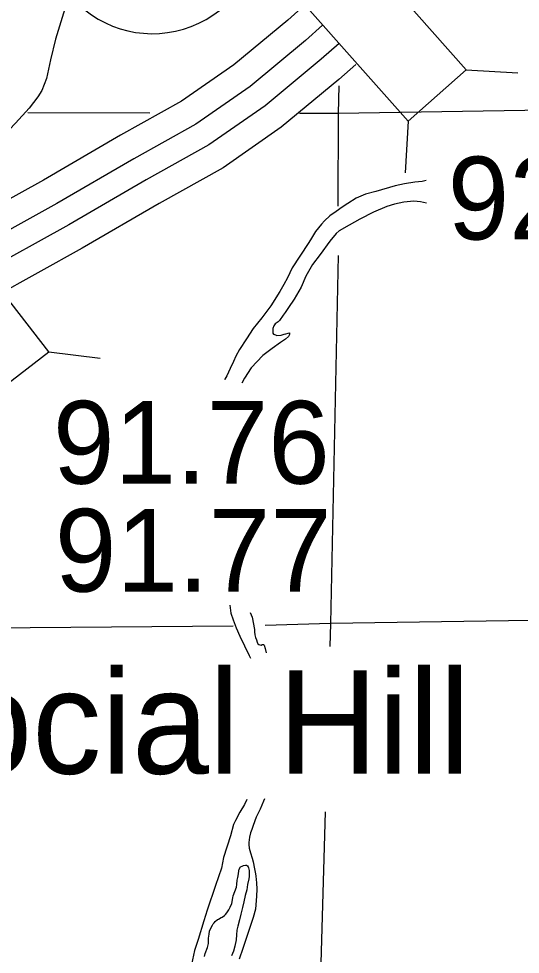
# Model space of a CAD drawing. Extents: x 22866 to 28196, y 1324810 to 1328105.
# Drawn here: x 24036.2 to 24121.3, y 1326735.6 to 1326894.3 of the extents above; entities that cross this region are included whole.
import ezdxf

# ---------------------------------------------------------------- set-up
doc = ezdxf.new("R2010")
doc.units = 0
for name, color, linetype in [('Level 10', 7, 'Continuous'), ('Level 19', 7, 'Continuous'), ('Level 20', 7, 'Continuous'), ('Level 24', 7, 'Continuous'), ('Level 4', 7, 'Continuous'), ('Level 5', 7, 'Continuous'), ('Level 58', 7, 'Continuous'), ('Level 9', 7, 'Continuous')]:
    doc.layers.add(name, color=color, linetype=linetype)

msp = doc.modelspace()

# ---------------------------------------------------------------- linework, layer by layer
at = {"layer": 'Level 10'}
msp.add_lwpolyline([(24043.99, 1326896), (24042.39, 1326890.87), (24041.54, 1326887.37), (24040.9, 1326884.19), (24040.08, 1326882.13), (24039.42, 1326881.07), (24037.95, 1326879.17), (24035.6, 1326876.6), (24032.53, 1326873.43), (24029.62, 1326870.47), (24026.22, 1326867.23), (24022.48, 1326863.48), (24018.35, 1326859.59), (24014.75, 1326856.32), (24011.73, 1326854.08), (24008.05, 1326851.01), (24004.29, 1326847.14), (24000.82, 1326843.16), (23997.45, 1326838.64), (23995.71, 1326836.61), (23993.79, 1326834.13), (23992.44, 1326832.42)], dxfattribs=at)
msp.add_lwpolyline([(24043.99, 1326896), (24042.39, 1326890.87), (24041.54, 1326887.37), (24040.9, 1326884.19), (24040.08, 1326882.13), (24039.42, 1326881.07), (24037.95, 1326879.17), (24035.6, 1326876.6), (24032.53, 1326873.43), (24029.62, 1326870.47), (24026.22, 1326867.23), (24022.48, 1326863.48), (24018.35, 1326859.59), (24014.75, 1326856.32), (24011.73, 1326854.08), (24008.05, 1326851.01), (24004.29, 1326847.14), (24000.82, 1326843.16), (23997.45, 1326838.64), (23995.71, 1326836.61), (23993.79, 1326834.13), (23992.44, 1326832.42)], dxfattribs=at)
at = {"layer": 'Level 19'}
for points in [[(24084.7, 1326896.62), (24081.85, 1326894.1), (24072.69, 1326886.51), (24063.82, 1326880.35), (24053.45, 1326874.56), (24040.37, 1326866.96), (24025.08, 1326858.49), (24021.08, 1326855.99), (24017.17, 1326852.96), (24013.54, 1326849.64), (24007.92, 1326844.77), (24003.92, 1326840.65), (23998.58, 1326834.2), (23993.67, 1326828.38), (23988.76, 1326822.21), (23982.91, 1326815.43)], [(24084.7, 1326896.62), (24081.85, 1326894.1), (24072.69, 1326886.51), (24063.82, 1326880.35), (24053.45, 1326874.56), (24040.37, 1326866.96), (24025.08, 1326858.49), (24021.08, 1326855.99), (24017.17, 1326852.96), (24013.54, 1326849.64), (24007.92, 1326844.77), (24003.92, 1326840.65), (23998.58, 1326834.2), (23993.67, 1326828.38), (23988.76, 1326822.21), (23982.91, 1326815.43)], [(24087.74, 1326893.21), (24084.83, 1326890.62), (24075.46, 1326882.86), (24066.24, 1326876.47), (24055.71, 1326870.59), (24042.63, 1326862.99), (24027.4, 1326854.55), (24023.7, 1326852.24), (24020.12, 1326849.46), (24016.58, 1326846.23), (24011.07, 1326841.45), (24007.33, 1326837.6), (24002.09, 1326831.27), (23997.21, 1326825.49), (23992.29, 1326819.29), (23986.36, 1326812.43)], [(24087.74, 1326893.21), (24084.83, 1326890.62), (24075.46, 1326882.86), (24066.24, 1326876.47), (24055.71, 1326870.59), (24042.63, 1326862.99), (24027.4, 1326854.55), (24023.7, 1326852.24), (24020.12, 1326849.46), (24016.58, 1326846.23), (24011.07, 1326841.45), (24007.33, 1326837.6), (24002.09, 1326831.27), (23997.21, 1326825.49), (23992.29, 1326819.29), (23986.36, 1326812.43)], [(24090.55, 1326890.14), (24087.53, 1326887.47), (24077.98, 1326879.55), (24068.45, 1326872.94), (24057.77, 1326866.98), (24044.68, 1326859.37), (24029.51, 1326850.97), (24026.08, 1326848.82), (24022.8, 1326846.28), (24019.35, 1326843.13), (24013.92, 1326838.42), (24010.42, 1326834.82), (24005.27, 1326828.61), (24000.42, 1326822.85), (23995.49, 1326816.64), (23989.68, 1326809.92)], [(24090.55, 1326890.14), (24087.53, 1326887.47), (24077.98, 1326879.55), (24068.45, 1326872.94), (24057.77, 1326866.98), (24044.68, 1326859.37), (24029.51, 1326850.97), (24026.08, 1326848.82), (24022.8, 1326846.28), (24019.35, 1326843.13), (24013.92, 1326838.42), (24010.42, 1326834.82), (24005.27, 1326828.61), (24000.42, 1326822.85), (23995.49, 1326816.64), (23989.68, 1326809.92)], [(24093.41, 1326886.57), (24090.51, 1326884), (24080.74, 1326875.91), (24070.87, 1326869.05), (24060.03, 1326863), (24046.94, 1326855.4), (24031.83, 1326847.03), (24028.7, 1326845.07), (24025.75, 1326842.78), (24022.39, 1326839.71), (24017.06, 1326835.1), (24013.83, 1326831.76), (24008.78, 1326825.67), (24003.96, 1326819.96), (23999.01, 1326813.72), (23992.97, 1326806.73)], [(24093.41, 1326886.57), (24090.51, 1326884), (24080.74, 1326875.91), (24070.87, 1326869.05), (24060.03, 1326863), (24046.94, 1326855.4), (24031.83, 1326847.03), (24028.7, 1326845.07), (24025.75, 1326842.78), (24022.39, 1326839.71), (24017.06, 1326835.1), (24013.83, 1326831.76), (24008.78, 1326825.67), (24003.96, 1326819.96), (23999.01, 1326813.72), (23992.97, 1326806.73)]]:
    msp.add_lwpolyline(points, dxfattribs=at)
at = {"layer": 'Level 20'}
for p, q in [((24112.14, 1326885.67), (24120.9, 1326885.15)), ((24112.14, 1326885.67), (24120.9, 1326885.15)), ((24102.29, 1326876.94), (24101.77, 1326868.17)), ((24102.29, 1326876.94), (24101.77, 1326868.17)), ((24041.25, 1326837.84), (24022.27, 1326862.33)), ((24041.25, 1326837.84), (24022.27, 1326862.33)), ((24030.85, 1326829.78), (24041.25, 1326837.84)), ((24030.85, 1326829.78), (24041.25, 1326837.84)), ((24041.25, 1326837.84), (24049.96, 1326836.74)), ((24041.25, 1326837.84), (24049.96, 1326836.74))]:
    msp.add_line(p, q, dxfattribs=at)
msp.add_lwpolyline([(24076.08, 1326906.49), (24102.29, 1326876.94), (24112.14, 1326885.67), (24085.94, 1326915.23)], close=True, dxfattribs=at)
msp.add_lwpolyline([(24076.08, 1326906.49), (24102.29, 1326876.94), (24112.14, 1326885.67), (24085.94, 1326915.23)], close=True, dxfattribs=at)
at = {"layer": 'Level 24'}
msp.add_arc((24058.88, 1326910.08), 18.29, 222.4098, 359.6767, dxfattribs=at)
msp.add_arc((24058.88, 1326910.08), 18.29, 222.4098, 359.6767, dxfattribs=at)
at = {"layer": 'Level 4'}
for points in [[(24258.9, 1326793.76), (24175.93, 1326793.02), (24089.1, 1326791.75), (24078.02, 1326791.42)], [(24258.9, 1326793.76), (24175.93, 1326793.02), (24089.1, 1326791.75), (24078.02, 1326791.42)], [(24072.58, 1326791.27), (24010.47, 1326790.77)], [(24072.58, 1326791.27), (24010.47, 1326790.77)]]:
    msp.add_lwpolyline(points, dxfattribs=at)
at = {"layer": 'Level 5'}
for points in [[(24090.49, 1326882.92), (24090.42, 1326878.23), (24090.35, 1326862.51)], [(24090.49, 1326882.92), (24090.42, 1326878.23), (24090.35, 1326862.51)], [(24160.82, 1326879.36), (24090.42, 1326878.23), (24083.82, 1326878.24)], [(24160.82, 1326879.36), (24090.42, 1326878.23), (24083.82, 1326878.24)], [(24058.44, 1326878.31), (24037.72, 1326878.36)], [(24058.44, 1326878.31), (24037.72, 1326878.36)], [(24090.38, 1326854.15), (24089.1, 1326791.75), (24088.99, 1326787.84)], [(24090.38, 1326854.15), (24089.1, 1326791.75), (24088.99, 1326787.84)], [(24088.18, 1326759.81), (24086.42, 1326698.59), (24085.9, 1326652.92)], [(24088.18, 1326759.81), (24086.42, 1326698.59), (24085.9, 1326652.92)]]:
    msp.add_lwpolyline(points, dxfattribs=at)
at = {"layer": 'Level 9'}
for points in [[(24105.34, 1326866.89), (24104.65, 1326866.73), (24103.43, 1326866.62), (24101.64, 1326866.34), (24100.05, 1326865.99), (24096.8, 1326865.03), (24095.05, 1326864.55), (24093.46, 1326863.87), (24092.04, 1326862.99), (24091.08, 1326862.38), (24090.06, 1326861.61), (24089, 1326860.9), (24088.05, 1326860.06), (24087.55, 1326859.49), (24086.53, 1326858.25), (24085.68, 1326856.84), (24085.32, 1326856.18), (24082.57, 1326852.06), (24081.79, 1326850.39), (24081.16, 1326849.25), (24080.48, 1326848.04), (24078.94, 1326845.63), (24077.46, 1326843.59)], [(24105.34, 1326866.89), (24104.65, 1326866.73), (24103.43, 1326866.62), (24101.64, 1326866.34), (24100.05, 1326865.99), (24096.8, 1326865.03), (24095.05, 1326864.55), (24093.46, 1326863.87), (24092.04, 1326862.99), (24091.08, 1326862.38), (24090.06, 1326861.61), (24089, 1326860.9), (24088.05, 1326860.06), (24087.55, 1326859.49), (24086.53, 1326858.25), (24085.68, 1326856.84), (24085.32, 1326856.18), (24082.57, 1326852.06), (24081.79, 1326850.39), (24081.16, 1326849.25), (24080.48, 1326848.04), (24078.94, 1326845.63), (24077.46, 1326843.59)], [(24105.39, 1326863.05), (24104.35, 1326863.26), (24103.25, 1326863.39), (24101.53, 1326863.21), (24099.94, 1326862.89), (24098.68, 1326862.48), (24096.4, 1326861.5), (24094.05, 1326860.35), (24092.27, 1326859.33), (24090.55, 1326858.35), (24090.06, 1326857.91), (24088.97, 1326856.57), (24087.33, 1326854.36), (24086.05, 1326852.65), (24084.9, 1326850.64), (24084.12, 1326848.81), (24082.94, 1326846.77), (24081.96, 1326845.33), (24081.4, 1326844.52), (24081.04, 1326844.05), (24080.45, 1326843.15), (24080.22, 1326842.91), (24079.69, 1326842.58), (24079.5, 1326842.24), (24079.33, 1326841.77), (24079.3, 1326841.44), (24079.31, 1326841.01), (24079.44, 1326840.81), (24079.74, 1326840.68), (24080.01, 1326840.61), (24080.7, 1326840.65), (24081.2, 1326840.79), (24081.53, 1326840.89), (24081.9, 1326841), (24082.16, 1326841.03), (24082.16, 1326840.77), (24081.97, 1326840.4), (24081.47, 1326839.99), (24080.58, 1326839.42), (24079.19, 1326838.41), (24077.58, 1326837.2), (24075.64, 1326835.08), (24074.49, 1326833.34), (24074.02, 1326832.5)], [(24105.39, 1326863.05), (24104.35, 1326863.26), (24103.25, 1326863.39), (24101.53, 1326863.21), (24099.94, 1326862.89), (24098.68, 1326862.48), (24096.4, 1326861.5), (24094.05, 1326860.35), (24092.27, 1326859.33), (24090.55, 1326858.35), (24090.06, 1326857.91), (24088.97, 1326856.57), (24087.33, 1326854.36), (24086.05, 1326852.65), (24084.9, 1326850.64), (24084.12, 1326848.81), (24082.94, 1326846.77), (24081.96, 1326845.33), (24081.4, 1326844.52), (24081.04, 1326844.05), (24080.45, 1326843.15), (24080.22, 1326842.91), (24079.69, 1326842.58), (24079.5, 1326842.24), (24079.33, 1326841.77), (24079.3, 1326841.44), (24079.31, 1326841.01), (24079.44, 1326840.81), (24079.74, 1326840.68), (24080.01, 1326840.61), (24080.7, 1326840.65), (24081.2, 1326840.79), (24081.53, 1326840.89), (24081.9, 1326841), (24082.16, 1326841.03), (24082.16, 1326840.77), (24081.97, 1326840.4), (24081.47, 1326839.99), (24080.58, 1326839.42), (24079.19, 1326838.41), (24077.58, 1326837.2), (24075.64, 1326835.08), (24074.49, 1326833.34), (24074.02, 1326832.5)], [(24077.46, 1326843.59), (24075.98, 1326841.78), (24074.83, 1326840), (24073.62, 1326838.2), (24073.03, 1326837.09), (24072.61, 1326836.16), (24072.05, 1326834.99), (24071.47, 1326833.75), (24071.17, 1326833.18), (24071.12, 1326833.07)], [(24077.46, 1326843.59), (24075.98, 1326841.78), (24074.83, 1326840), (24073.62, 1326838.2), (24073.03, 1326837.09), (24072.61, 1326836.16), (24072.05, 1326834.99), (24071.47, 1326833.75), (24071.17, 1326833.18), (24071.12, 1326833.07)], [(24071.99, 1326794.86), (24072.19, 1326793.47), (24072.57, 1326792.34), (24073.08, 1326791.01), (24073.69, 1326789.58), (24074.5, 1326787.96), (24075.27, 1326786.33), (24075.5, 1326785.85)], [(24071.99, 1326794.86), (24072.19, 1326793.47), (24072.57, 1326792.34), (24073.08, 1326791.01), (24073.69, 1326789.58), (24074.5, 1326787.96), (24075.27, 1326786.33), (24075.5, 1326785.85)], [(24075.47, 1326793.61), (24075.78, 1326792.8), (24076.17, 1326790.7), (24076.2, 1326790.3), (24076.27, 1326789.84), (24076.38, 1326789.34), (24076.51, 1326788.94), (24076.65, 1326788.58), (24076.78, 1326788.28), (24076.92, 1326788.18), (24077.12, 1326788.11), (24077.32, 1326788.08), (24077.52, 1326788.18), (24077.71, 1326788.19), (24077.82, 1326788.05), (24077.99, 1326787.49), (24078.18, 1326786.77)], [(24075.47, 1326793.61), (24075.78, 1326792.8), (24076.17, 1326790.7), (24076.2, 1326790.3), (24076.27, 1326789.84), (24076.38, 1326789.34), (24076.51, 1326788.94), (24076.65, 1326788.58), (24076.78, 1326788.28), (24076.92, 1326788.18), (24077.12, 1326788.11), (24077.32, 1326788.08), (24077.52, 1326788.18), (24077.71, 1326788.19), (24077.82, 1326788.05), (24077.99, 1326787.49), (24078.18, 1326786.77)], [(24074.91, 1326761.87), (24074.52, 1326761.05), (24073.7, 1326759.72), (24072.95, 1326758.31), (24072.62, 1326757.64), (24072.11, 1326755.71), (24070.94, 1326752.03), (24070.56, 1326750.23), (24069.59, 1326747.29), (24068.16, 1326743.12), (24067.58, 1326741.32), (24066.61, 1326738.11), (24066.02, 1326736.24), (24065.35, 1326733.11)], [(24074.91, 1326761.87), (24074.52, 1326761.05), (24073.7, 1326759.72), (24072.95, 1326758.31), (24072.62, 1326757.64), (24072.11, 1326755.71), (24070.94, 1326752.03), (24070.56, 1326750.23), (24069.59, 1326747.29), (24068.16, 1326743.12), (24067.58, 1326741.32), (24066.61, 1326738.11), (24066.02, 1326736.24), (24065.35, 1326733.11)], [(24077.86, 1326761.98), (24077.7, 1326761.61), (24077.15, 1326760.24), (24076.49, 1326758.87), (24075.97, 1326757.47), (24075.71, 1326756.8), (24075.52, 1326756.2), (24075.33, 1326755.47), (24075.2, 1326754.6), (24075.2, 1326754.23), (24075.28, 1326753.6), (24075.51, 1326752.81), (24075.82, 1326751.94), (24075.96, 1326751.28), (24076.17, 1326750.11), (24076.34, 1326749.28), (24076.41, 1326748.85), (24076.52, 1326747.75), (24076.56, 1326746.65), (24076.54, 1326745.46), (24076.36, 1326743.29), (24075.97, 1326741.86), (24075.39, 1326740.15), (24074.71, 1326738.15), (24074.22, 1326736.58), (24073.6, 1326734.81)], [(24077.86, 1326761.98), (24077.7, 1326761.61), (24077.15, 1326760.24), (24076.49, 1326758.87), (24075.97, 1326757.47), (24075.71, 1326756.8), (24075.52, 1326756.2), (24075.33, 1326755.47), (24075.2, 1326754.6), (24075.2, 1326754.23), (24075.28, 1326753.6), (24075.51, 1326752.81), (24075.82, 1326751.94), (24075.96, 1326751.28), (24076.17, 1326750.11), (24076.34, 1326749.28), (24076.41, 1326748.85), (24076.52, 1326747.75), (24076.56, 1326746.65), (24076.54, 1326745.46), (24076.36, 1326743.29), (24075.97, 1326741.86), (24075.39, 1326740.15), (24074.71, 1326738.15), (24074.22, 1326736.58), (24073.6, 1326734.81)], [(24072.59, 1326745.52), (24073.11, 1326747.02), (24073.17, 1326747.46), (24073.26, 1326748.22), (24073.36, 1326748.66), (24073.45, 1326749.29), (24073.55, 1326749.79), (24073.61, 1326750.06), (24073.84, 1326750.43), (24074.07, 1326750.56), (24074.3, 1326750.66), (24074.67, 1326750.73), (24074.83, 1326750.74), (24075, 1326750.64), (24075.1, 1326750.44), (24075.17, 1326750.27), (24075.21, 1326750.07), (24075.27, 1326749.81), (24075.28, 1326749.57), (24075.31, 1326749.24), (24075.28, 1326748.84), (24075.22, 1326748.44), (24075.03, 1326747.47), (24074.87, 1326746.54), (24074.58, 1326745.61), (24074.39, 1326744.54), (24074.16, 1326743.54), (24073.87, 1326742.4), (24073.65, 1326741.44), (24073.36, 1326740.37), (24073.2, 1326739.7), (24073.14, 1326738.93), (24073.05, 1326738.07), (24072.86, 1326736.97), (24072.6, 1326736.13), (24072.31, 1326735.36)], [(24072.59, 1326745.52), (24073.11, 1326747.02), (24073.17, 1326747.46), (24073.26, 1326748.22), (24073.36, 1326748.66), (24073.45, 1326749.29), (24073.55, 1326749.79), (24073.61, 1326750.06), (24073.84, 1326750.43), (24074.07, 1326750.56), (24074.3, 1326750.66), (24074.67, 1326750.73), (24074.83, 1326750.74), (24075, 1326750.64), (24075.1, 1326750.44), (24075.17, 1326750.27), (24075.21, 1326750.07), (24075.27, 1326749.81), (24075.28, 1326749.57), (24075.31, 1326749.24), (24075.28, 1326748.84), (24075.22, 1326748.44), (24075.03, 1326747.47), (24074.87, 1326746.54), (24074.58, 1326745.61), (24074.39, 1326744.54), (24074.16, 1326743.54), (24073.87, 1326742.4), (24073.65, 1326741.44), (24073.36, 1326740.37), (24073.2, 1326739.7), (24073.14, 1326738.93), (24073.05, 1326738.07), (24072.86, 1326736.97), (24072.6, 1326736.13), (24072.31, 1326735.36)], [(24068.21, 1326736.79), (24068.37, 1326737.43), (24068.4, 1326738.33), (24068.49, 1326739.06), (24068.55, 1326739.53), (24068.75, 1326740.03), (24069.04, 1326740.56), (24069.17, 1326740.8), (24069.34, 1326740.97), (24069.54, 1326741.2), (24069.93, 1326741.5), (24070.1, 1326741.6), (24070.53, 1326741.84), (24070.69, 1326741.94), (24071.09, 1326742.21), (24071.25, 1326742.38), (24071.48, 1326742.65), (24071.84, 1326743.15), (24072.07, 1326743.62), (24072.33, 1326744.25), (24072.52, 1326745.19), (24072.59, 1326745.52)], [(24068.21, 1326736.79), (24068.37, 1326737.43), (24068.4, 1326738.33), (24068.49, 1326739.06), (24068.55, 1326739.53), (24068.75, 1326740.03), (24069.04, 1326740.56), (24069.17, 1326740.8), (24069.34, 1326740.97), (24069.54, 1326741.2), (24069.93, 1326741.5), (24070.1, 1326741.6), (24070.53, 1326741.84), (24070.69, 1326741.94), (24071.09, 1326742.21), (24071.25, 1326742.38), (24071.48, 1326742.65), (24071.84, 1326743.15), (24072.07, 1326743.62), (24072.33, 1326744.25), (24072.52, 1326745.19), (24072.59, 1326745.52)], [(24067.69, 1326735.22), (24067.82, 1326735.73), (24068.21, 1326736.79)], [(24067.69, 1326735.22), (24067.82, 1326735.73), (24068.21, 1326736.79)]]:
    msp.add_lwpolyline(points, dxfattribs=at)

# ---------------------------------------------------------------- texts
at = {"layer": 'Level 24'}
msp.add_text('Social Hill', height=17.5553, dxfattribs=at).set_placement((24009.74, 1326766.25))
msp.add_text('Social Hill', height=17.5553, dxfattribs=at).set_placement((24009.74, 1326766.25))
at = {"layer": 'Level 58'}
for s, height, p in [('92.75(U.P.)', 14.0442, (24108.99, 1326856.88)), ('92.75(U.P.)', 14.0442, (24108.99, 1326856.88)), ('91.76', 14.044, (24041.97, 1326815.45)), ('91.76', 14.044, (24041.97, 1326815.45)), ('91.77', 14.044, (24042.3, 1326797.14)), ('91.77', 14.044, (24042.3, 1326797.14))]:
    msp.add_text(s, height=height, dxfattribs=at).set_placement(p)

doc.saveas('drawing.dxf')
